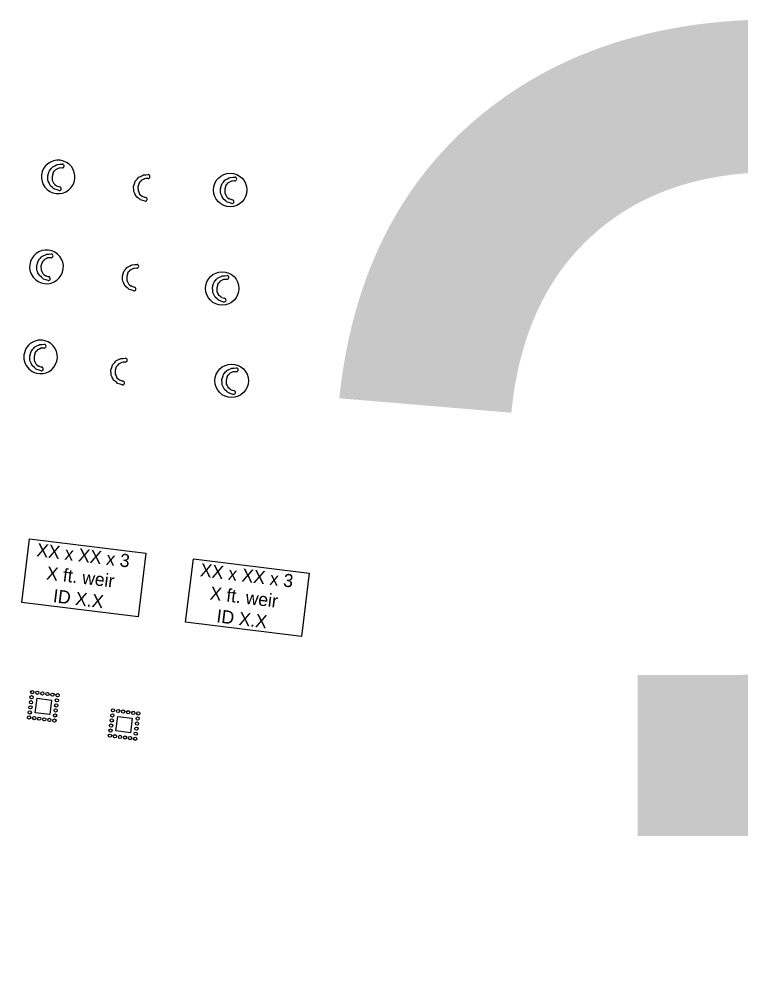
# Model space of a CAD drawing. Extents: x 2470000 to 2520000, y 340000 to 380000.
# Drawn here: x 2483280 to 2483776, y 373794 to 374460 of the extents above; entities that cross this region are included whole.
import ezdxf

# ---------------------------------------------------------------- set-up
doc = ezdxf.new("R2010")
doc.units = 0
for name, color, linetype in [('Coir Fiber Wattle Both CELL', 7, 'Continuous'), ('Coir Fiber Wattle CG CELL', 7, 'Continuous'), ('Coir Fiber Wattle Final CELL', 7, 'Continuous'), ('Coir Fiber Wattle with PAM Both CELL', 7, 'Continuous'), ('Coir Fiber Wattle with PAM CG CELL', 7, 'Continuous'), ('Coir Fiber Wattle with PAM Final CELL', 7, 'Continuous'), ('Prop Structure Anchor Unit CELL', 7, 'Continuous'), ('Scratch_Level_5', 7, 'Continuous'), ('Scratch_Level_6', 7, 'Continuous'), ('Sediment Dam B Note Both CELL', 7, 'Continuous'), ('Sediment Dam B Note Final CELL', 7, 'Continuous'), ('Wattle with PAM Both CELL', 7, 'Continuous'), ('Wattle with PAM CG CELL', 7, 'Continuous'), ('Wattle with PAM Final CELL', 7, 'Continuous')]:
    doc.layers.add(name, color=color, linetype=linetype)

msp = doc.modelspace()

# ---------------------------------------------------------------- linework, layer by layer
at = {"layer": 'Coir Fiber Wattle Both CELL'}
for p, q in [((2483354.84, 374285.25), (2483354.07, 374282.74)), ((2483354.07, 374282.73), (2483354.07, 374282.74)), ((2483354.07, 374282.73), (2483354.19, 374280.19)), ((2483354.84, 374285.25), (2483355.59, 374286.18)), ((2483356.29, 374287.05), (2483355.59, 374286.18)), ((2483356.29, 374287.05), (2483356.44, 374287.23)), ((2483357.74, 374287.88), (2483356.44, 374287.23)), ((2483358.72, 374288.37), (2483357.74, 374287.88)), ((2483359.51, 374288.41), (2483358.72, 374288.37)), ((2483361.07, 374288.5), (2483359.51, 374288.41)), ((2483354.19, 374280.19), (2483354.69, 374279.1)), ((2483354.69, 374279.1), (2483355.3, 374277.79)), ((2483355.3, 374277.79), (2483356.09, 374277.13)), ((2483356.09, 374277.13), (2483357.23, 374276.18)), ((2483357.54, 374276.08), (2483357.23, 374276.18)), ((2483357.54, 374276.08), (2483359.32, 374275.51))]:
    msp.add_line(p, q, dxfattribs=at)
msp.add_lwpolyline([(2483359, 374272.93), (2483357.51, 374273.39), (2483355.77, 374273.92), (2483355.12, 374274.45), (2483354.35, 374275.09), (2483352.96, 374276.24), (2483352.94, 374276.27), (2483352.75, 374276.67), (2483352.72, 374276.74), (2483352.29, 374277.59), (2483352, 374278.19), (2483351.36, 374279.51), (2483351.29, 374280.55), (2483351.12, 374283.09), (2483351.12, 374283.1), (2483351.93, 374285.61), (2483352.24, 374286.59), (2483352.98, 374287.45), (2483353.13, 374287.63), (2483353.76, 374288.37), (2483354.23, 374288.92), (2483354.35, 374289.05), (2483354.58, 374289.33), (2483354.59, 374289.33), (2483355.95, 374289.99), (2483357.16, 374290.57), (2483357.89, 374290.93), (2483359.64, 374291.05), (2483361.19, 374291.16)], dxfattribs=at)
for centre, radius, start in [((2483361.02, 374289.83), 1.33, 271.87949), ((2483359.16, 374274.22), 1.3, 262.99213)]:
    msp.add_arc(centre, radius, start, 82.99213, dxfattribs=at)
at = {"layer": 'Coir Fiber Wattle CG CELL'}
for p, q in [((2483363.97, 374348.72), (2483363.27, 374347.85)), ((2483363.97, 374348.72), (2483364.12, 374348.9)), ((2483365.42, 374349.55), (2483364.12, 374348.9)), ((2483366.41, 374350.04), (2483365.42, 374349.55)), ((2483367.2, 374350.08), (2483366.41, 374350.04)), ((2483368.75, 374350.17), (2483367.2, 374350.08)), ((2483362.53, 374346.92), (2483361.75, 374344.41)), ((2483361.75, 374344.4), (2483361.75, 374344.41)), ((2483361.75, 374344.4), (2483361.87, 374341.86)), ((2483362.53, 374346.92), (2483363.27, 374347.85)), ((2483361.87, 374341.86), (2483362.37, 374340.77)), ((2483362.37, 374340.77), (2483362.98, 374339.45)), ((2483362.98, 374339.45), (2483363.77, 374338.8)), ((2483363.77, 374338.8), (2483364.91, 374337.85)), ((2483365.23, 374337.75), (2483364.91, 374337.85)), ((2483365.23, 374337.75), (2483367, 374337.18))]:
    msp.add_line(p, q, dxfattribs=at)
msp.add_lwpolyline([(2483366.68, 374334.6), (2483365.19, 374335.06), (2483363.45, 374335.58), (2483362.81, 374336.12), (2483362.03, 374336.76), (2483360.64, 374337.9), (2483360.63, 374337.94), (2483360.43, 374338.34), (2483360.4, 374338.4), (2483359.98, 374339.26), (2483359.68, 374339.86), (2483359.04, 374341.18), (2483358.97, 374342.22), (2483358.8, 374344.76), (2483358.8, 374344.77), (2483359.61, 374347.28), (2483359.93, 374348.26), (2483360.66, 374349.12), (2483360.82, 374349.3), (2483361.44, 374350.03), (2483361.92, 374350.59), (2483362.03, 374350.72), (2483362.27, 374351), (2483362.27, 374351), (2483363.63, 374351.66), (2483364.84, 374352.24), (2483365.57, 374352.6), (2483367.32, 374352.72), (2483368.87, 374352.83)], dxfattribs=at)
for centre, radius, start in [((2483368.7, 374351.5), 1.33, 271.87949), ((2483366.84, 374335.89), 1.3, 262.99213)]:
    msp.add_arc(centre, radius, start, 82.99213, dxfattribs=at)
at = {"layer": 'Coir Fiber Wattle Final CELL'}
for p, q in [((2483348.35, 374222.46), (2483347.65, 374221.6)), ((2483348.35, 374222.46), (2483348.5, 374222.65)), ((2483349.8, 374223.29), (2483348.5, 374222.65)), ((2483350.79, 374223.78), (2483349.8, 374223.29)), ((2483351.58, 374223.83), (2483350.79, 374223.78)), ((2483353.13, 374223.91), (2483351.58, 374223.83)), ((2483346.91, 374220.67), (2483346.13, 374218.16)), ((2483346.13, 374218.14), (2483346.13, 374218.16)), ((2483346.13, 374218.14), (2483346.25, 374215.61)), ((2483346.25, 374215.61), (2483346.75, 374214.51)), ((2483346.91, 374220.67), (2483347.65, 374221.6)), ((2483346.75, 374214.51), (2483347.36, 374213.2)), ((2483347.36, 374213.2), (2483348.15, 374212.54)), ((2483348.15, 374212.54), (2483349.29, 374211.6)), ((2483349.6, 374211.5), (2483349.29, 374211.6)), ((2483349.6, 374211.5), (2483351.38, 374210.93))]:
    msp.add_line(p, q, dxfattribs=at)
msp.add_lwpolyline([(2483351.06, 374208.35), (2483349.57, 374208.8), (2483347.83, 374209.33), (2483347.19, 374209.86), (2483346.41, 374210.51), (2483345.02, 374211.65), (2483345.01, 374211.69), (2483344.81, 374212.08), (2483344.78, 374212.15), (2483344.36, 374213.01), (2483344.06, 374213.61), (2483343.42, 374214.92), (2483343.35, 374215.96), (2483343.18, 374218.51), (2483343.18, 374218.52), (2483343.99, 374221.03), (2483344.31, 374222.01), (2483345.04, 374222.87), (2483345.19, 374223.05), (2483345.82, 374223.78), (2483346.29, 374224.34), (2483346.41, 374224.47), (2483346.65, 374224.74), (2483346.65, 374224.75), (2483348.01, 374225.41), (2483349.22, 374225.99), (2483349.95, 374226.34), (2483351.7, 374226.46), (2483353.25, 374226.57)], dxfattribs=at)
for centre, radius, start in [((2483353.08, 374225.25), 1.33, 271.87949), ((2483351.22, 374209.64), 1.3, 262.99213)]:
    msp.add_arc(centre, radius, start, 82.99213, dxfattribs=at)
at = {"layer": 'Coir Fiber Wattle with PAM Both CELL'}
for p, q in [((2483416.69, 374277.58), (2483415.92, 374275.06)), ((2483416.69, 374277.58), (2483417.44, 374278.5)), ((2483418.14, 374279.37), (2483417.44, 374278.5)), ((2483418.14, 374279.37), (2483418.28, 374279.55)), ((2483419.58, 374280.2), (2483418.28, 374279.55)), ((2483420.57, 374280.69), (2483419.58, 374280.2)), ((2483421.36, 374280.74), (2483420.57, 374280.69)), ((2483422.91, 374280.82), (2483421.36, 374280.74)), ((2483415.92, 374275.05), (2483415.92, 374275.06)), ((2483415.92, 374275.05), (2483416.03, 374272.51)), ((2483416.03, 374272.51), (2483416.54, 374271.42)), ((2483416.54, 374271.42), (2483417.15, 374270.11)), ((2483417.15, 374270.11), (2483417.94, 374269.45)), ((2483417.94, 374269.45), (2483419.07, 374268.5)), ((2483419.39, 374268.4), (2483419.07, 374268.5)), ((2483419.39, 374268.4), (2483421.16, 374267.83))]:
    msp.add_line(p, q, dxfattribs=at)
msp.add_lwpolyline([(2483420.85, 374265.26), (2483419.35, 374265.71), (2483417.62, 374266.24), (2483416.97, 374266.77), (2483416.19, 374267.41), (2483414.81, 374268.56), (2483414.79, 374268.59), (2483414.6, 374268.99), (2483414.56, 374269.06), (2483414.14, 374269.92), (2483413.85, 374270.51), (2483413.2, 374271.83), (2483413.13, 374272.87), (2483412.97, 374275.41), (2483412.97, 374275.42), (2483413.78, 374277.94), (2483414.09, 374278.92), (2483414.83, 374279.78), (2483414.98, 374279.96), (2483415.61, 374280.69), (2483416.08, 374281.24), (2483416.19, 374281.37), (2483416.43, 374281.65), (2483416.44, 374281.66), (2483417.8, 374282.31), (2483419.01, 374282.9), (2483419.74, 374283.25), (2483421.49, 374283.37), (2483423.03, 374283.48)], dxfattribs=at)
msp.add_circle((2483419.69, 374274.57), 11.5, dxfattribs=at)
for centre, radius, start in [((2483422.87, 374282.15), 1.33, 271.87949), ((2483421, 374266.54), 1.3, 262.99213)]:
    msp.add_arc(centre, radius, start, 82.99213, dxfattribs=at)
at = {"layer": 'Coir Fiber Wattle with PAM CG CELL'}
for p, q in [((2483422.17, 374345.29), (2483421.39, 374342.78)), ((2483421.39, 374342.77), (2483421.39, 374342.78)), ((2483421.39, 374342.77), (2483421.51, 374340.23)), ((2483422.17, 374345.29), (2483422.91, 374346.22)), ((2483423.61, 374347.08), (2483422.91, 374346.22)), ((2483423.61, 374347.08), (2483423.76, 374347.27)), ((2483425.06, 374347.91), (2483423.76, 374347.27)), ((2483426.05, 374348.4), (2483425.06, 374347.91)), ((2483426.84, 374348.45), (2483426.05, 374348.4)), ((2483428.39, 374348.53), (2483426.84, 374348.45)), ((2483421.51, 374340.23), (2483422.01, 374339.13)), ((2483422.01, 374339.13), (2483422.62, 374337.82)), ((2483422.62, 374337.82), (2483423.41, 374337.16)), ((2483423.41, 374337.16), (2483424.55, 374336.22)), ((2483424.86, 374336.12), (2483424.55, 374336.22)), ((2483424.86, 374336.12), (2483426.64, 374335.55))]:
    msp.add_line(p, q, dxfattribs=at)
msp.add_lwpolyline([(2483426.32, 374332.97), (2483424.83, 374333.42), (2483423.09, 374333.95), (2483422.45, 374334.48), (2483421.67, 374335.13), (2483420.28, 374336.27), (2483420.27, 374336.31), (2483420.07, 374336.71), (2483420.04, 374336.77), (2483419.62, 374337.63), (2483419.32, 374338.23), (2483418.68, 374339.54), (2483418.61, 374340.58), (2483418.44, 374343.13), (2483418.44, 374343.14), (2483419.25, 374345.65), (2483419.57, 374346.63), (2483420.3, 374347.49), (2483420.45, 374347.67), (2483421.08, 374348.4), (2483421.55, 374348.96), (2483421.67, 374349.09), (2483421.91, 374349.37), (2483421.91, 374349.37), (2483423.27, 374350.03), (2483424.48, 374350.61), (2483425.21, 374350.96), (2483426.96, 374351.09), (2483428.51, 374351.19)], dxfattribs=at)
msp.add_circle((2483425.16, 374342.29), 11.5, dxfattribs=at)
for centre, radius, start in [((2483428.34, 374349.87), 1.33, 271.87949), ((2483426.48, 374334.26), 1.3, 262.99213)]:
    msp.add_arc(centre, radius, start, 82.99213, dxfattribs=at)
at = {"layer": 'Coir Fiber Wattle with PAM Final CELL'}
for p, q in [((2483424.58, 374215.89), (2483423.88, 374215.02)), ((2483424.58, 374215.89), (2483424.73, 374216.07)), ((2483426.03, 374216.72), (2483424.73, 374216.07)), ((2483427.02, 374217.21), (2483426.03, 374216.72)), ((2483427.81, 374217.25), (2483427.02, 374217.21)), ((2483429.36, 374217.34), (2483427.81, 374217.25)), ((2483423.14, 374214.1), (2483422.36, 374211.58)), ((2483422.36, 374211.57), (2483422.36, 374211.58)), ((2483422.36, 374211.57), (2483422.48, 374209.03)), ((2483422.48, 374209.03), (2483422.98, 374207.94)), ((2483423.14, 374214.1), (2483423.88, 374215.02)), ((2483422.98, 374207.94), (2483423.59, 374206.63)), ((2483423.59, 374206.63), (2483424.38, 374205.97)), ((2483424.38, 374205.97), (2483425.52, 374205.02)), ((2483425.83, 374204.92), (2483425.52, 374205.02)), ((2483425.83, 374204.92), (2483427.61, 374204.35))]:
    msp.add_line(p, q, dxfattribs=at)
msp.add_lwpolyline([(2483427.29, 374201.77), (2483425.8, 374202.23), (2483424.06, 374202.76), (2483423.42, 374203.29), (2483422.64, 374203.93), (2483421.25, 374205.08), (2483421.24, 374205.11), (2483421.04, 374205.51), (2483421.01, 374205.58), (2483420.59, 374206.43), (2483420.29, 374207.03), (2483419.65, 374208.35), (2483419.58, 374209.39), (2483419.41, 374211.93), (2483419.41, 374211.94), (2483420.22, 374214.45), (2483420.54, 374215.43), (2483421.27, 374216.29), (2483421.42, 374216.48), (2483422.05, 374217.21), (2483422.52, 374217.76), (2483422.64, 374217.89), (2483422.87, 374218.17), (2483422.88, 374218.17), (2483424.24, 374218.83), (2483425.45, 374219.42), (2483426.18, 374219.77), (2483427.93, 374219.89), (2483429.48, 374220)], dxfattribs=at)
msp.add_circle((2483426.13, 374211.09), 11.5, dxfattribs=at)
for centre, radius, start in [((2483429.31, 374218.67), 1.33, 271.87949), ((2483427.45, 374203.06), 1.3, 262.99213)]:
    msp.add_arc(centre, radius, start, 82.99213, dxfattribs=at)
at = {"layer": 'Prop Structure Anchor Unit CELL'}
msp.add_lwpolyline([(2483292.48, 373992.86), (2483302.4, 373991.64), (2483301.18, 373981.72), (2483291.26, 373982.95)], close=True, dxfattribs=at)
for centre in [(2483289.21, 373997.06), (2483292.68, 373996.64), (2483296.15, 373996.21), (2483299.63, 373995.78), (2483303.1, 373995.35), (2483306.57, 373994.93), (2483288.35, 373990.11), (2483288.78, 373993.59), (2483306.15, 373991.45), (2483287.5, 373983.17), (2483287.92, 373986.64), (2483305.29, 373984.5), (2483305.72, 373987.98), (2483287.07, 373979.69), (2483290.54, 373979.27), (2483294.02, 373978.84), (2483297.49, 373978.41), (2483300.96, 373977.98), (2483304.44, 373977.56), (2483304.87, 373981.03)]:
    msp.add_circle(centre, 1.12, dxfattribs=at)
at = {"layer": 'Scratch_Level_5'}
msp.add_lwpolyline([(2483347.93, 373980.35), (2483357.85, 373979.13), (2483356.63, 373969.2), (2483346.71, 373970.44)], close=True, dxfattribs=at)
for centre in [(2483344.66, 373984.55), (2483348.13, 373984.12), (2483351.61, 373983.69), (2483355.08, 373983.27), (2483358.55, 373982.84), (2483362.03, 373982.41), (2483343.8, 373977.6), (2483344.23, 373981.07), (2483361.17, 373975.46), (2483361.6, 373978.94), (2483342.95, 373970.65), (2483343.38, 373974.13), (2483360.32, 373968.52), (2483360.74, 373971.99), (2483342.52, 373967.18), (2483345.99, 373966.75), (2483349.47, 373966.32), (2483352.94, 373965.9), (2483356.42, 373965.47), (2483359.89, 373965.04)]:
    msp.add_circle(centre, 1.12, dxfattribs=at)
at = {"layer": 'Sediment Dam B Note Both CELL'}
msp.add_lwpolyline([(2483287.36, 374102.39), (2483367.29, 374092.57), (2483361.92, 374048.92), (2483281.99, 374058.75)], close=True, dxfattribs=at)
at = {"layer": 'Sediment Dam B Note Final CELL'}
msp.add_lwpolyline([(2483399.86, 374088.73), (2483479.46, 374078.95), (2483474.09, 374035.3), (2483394.49, 374045.09)], close=True, dxfattribs=at)
at = {"layer": 'Wattle with PAM Both CELL'}
for p, q in [((2483299.87, 374295.53), (2483298.88, 374295.04)), ((2483300.66, 374295.57), (2483299.87, 374295.53)), ((2483302.21, 374295.66), (2483300.66, 374295.57)), ((2483295.99, 374292.41), (2483295.21, 374289.9)), ((2483295.21, 374289.89), (2483295.21, 374289.9)), ((2483295.21, 374289.89), (2483295.33, 374287.35)), ((2483295.99, 374292.41), (2483296.73, 374293.34)), ((2483297.43, 374294.21), (2483296.73, 374293.34)), ((2483297.43, 374294.21), (2483297.58, 374294.39)), ((2483298.88, 374295.04), (2483297.58, 374294.39)), ((2483295.33, 374287.35), (2483295.83, 374286.26)), ((2483295.83, 374286.26), (2483296.44, 374284.95)), ((2483296.44, 374284.95), (2483297.23, 374284.29)), ((2483297.23, 374284.29), (2483298.37, 374283.34)), ((2483298.69, 374283.24), (2483298.37, 374283.34)), ((2483298.69, 374283.24), (2483300.46, 374282.67))]:
    msp.add_line(p, q, dxfattribs=at)
msp.add_lwpolyline([(2483300.14, 374280.09), (2483298.65, 374280.55), (2483296.91, 374281.07), (2483296.27, 374281.61), (2483295.49, 374282.25), (2483294.1, 374283.39), (2483294.09, 374283.43), (2483293.89, 374283.83), (2483293.86, 374283.89), (2483293.44, 374284.75), (2483293.14, 374285.35), (2483292.5, 374286.67), (2483292.43, 374287.71), (2483292.26, 374290.25), (2483292.26, 374290.26), (2483293.07, 374292.77), (2483293.39, 374293.75), (2483294.12, 374294.61), (2483294.28, 374294.79), (2483294.9, 374295.52), (2483295.37, 374296.08), (2483295.49, 374296.21), (2483295.73, 374296.49), (2483295.73, 374296.49), (2483297.09, 374297.15), (2483298.3, 374297.73), (2483299.03, 374298.09), (2483300.78, 374298.21), (2483302.33, 374298.32)], dxfattribs=at)
for centre, radius, start, end in [((2483298.98, 374289.41), 11.62, 82.99213, 262.99213), ((2483298.98, 374289.41), 11.62, 262.99213, 82.99213), ((2483302.16, 374296.99), 1.33, 271.87949, 82.99213), ((2483300.3, 374281.38), 1.3, 262.99213, 82.99213)]:
    msp.add_arc(centre, radius, start, end, dxfattribs=at)
at = {"layer": 'Wattle with PAM CG CELL'}
for p, q in [((2483305.02, 374355.96), (2483304.32, 374355.1)), ((2483305.02, 374355.96), (2483304.32, 374355.1)), ((2483305.02, 374355.96), (2483305.17, 374356.14)), ((2483305.02, 374355.96), (2483305.17, 374356.14)), ((2483306.47, 374356.79), (2483305.17, 374356.14)), ((2483306.47, 374356.79), (2483305.17, 374356.14)), ((2483307.46, 374357.28), (2483306.47, 374356.79)), ((2483307.46, 374357.28), (2483306.47, 374356.79)), ((2483308.25, 374357.33), (2483307.46, 374357.28)), ((2483308.25, 374357.33), (2483307.46, 374357.28)), ((2483309.8, 374357.41), (2483308.25, 374357.33)), ((2483309.8, 374357.41), (2483308.25, 374357.33)), ((2483303.58, 374354.17), (2483302.8, 374351.66)), ((2483303.58, 374354.17), (2483302.8, 374351.66)), ((2483302.8, 374351.64), (2483302.8, 374351.66)), ((2483302.8, 374351.64), (2483302.8, 374351.66)), ((2483302.8, 374351.64), (2483302.92, 374349.1)), ((2483302.8, 374351.64), (2483302.92, 374349.1)), ((2483302.92, 374349.1), (2483303.42, 374348.01)), ((2483302.92, 374349.1), (2483303.42, 374348.01)), ((2483303.58, 374354.17), (2483304.32, 374355.1)), ((2483303.58, 374354.17), (2483304.32, 374355.1)), ((2483303.42, 374348.01), (2483304.03, 374346.7)), ((2483303.42, 374348.01), (2483304.03, 374346.7)), ((2483304.03, 374346.7), (2483304.82, 374346.04)), ((2483304.03, 374346.7), (2483304.82, 374346.04)), ((2483304.82, 374346.04), (2483305.96, 374345.1)), ((2483304.82, 374346.04), (2483305.96, 374345.1)), ((2483306.28, 374344.99), (2483305.96, 374345.1)), ((2483306.28, 374344.99), (2483305.96, 374345.1)), ((2483306.28, 374344.99), (2483308.05, 374344.43)), ((2483306.28, 374344.99), (2483308.05, 374344.43))]:
    msp.add_line(p, q, dxfattribs=at)
msp.add_lwpolyline([(2483307.73, 374341.85), (2483306.24, 374342.3), (2483304.5, 374342.83), (2483303.86, 374343.36), (2483303.08, 374344.01), (2483301.7, 374345.15), (2483301.68, 374345.19), (2483301.48, 374345.58), (2483301.45, 374345.65), (2483301.03, 374346.51), (2483300.73, 374347.11), (2483300.09, 374348.42), (2483300.02, 374349.46), (2483299.85, 374352.01), (2483299.86, 374352.02), (2483300.66, 374354.53), (2483300.98, 374355.51), (2483301.71, 374356.37), (2483301.87, 374356.55), (2483302.49, 374357.28), (2483302.97, 374357.84), (2483303.08, 374357.96), (2483303.32, 374358.24), (2483303.32, 374358.25), (2483304.68, 374358.91), (2483305.89, 374359.49), (2483306.62, 374359.84), (2483308.37, 374359.96), (2483309.92, 374360.07)], dxfattribs=at)
msp.add_lwpolyline([(2483307.73, 374341.85), (2483306.24, 374342.3), (2483304.5, 374342.83), (2483303.86, 374343.36), (2483303.08, 374344.01), (2483301.7, 374345.15), (2483301.68, 374345.19), (2483301.48, 374345.58), (2483301.45, 374345.65), (2483301.03, 374346.51), (2483300.73, 374347.11), (2483300.09, 374348.42), (2483300.02, 374349.46), (2483299.85, 374352.01), (2483299.86, 374352.02), (2483300.66, 374354.53), (2483300.98, 374355.51), (2483301.71, 374356.37), (2483301.87, 374356.55), (2483302.49, 374357.28), (2483302.97, 374357.84), (2483303.08, 374357.96), (2483303.32, 374358.24), (2483303.32, 374358.25), (2483304.68, 374358.91), (2483305.89, 374359.49), (2483306.62, 374359.84), (2483308.37, 374359.96), (2483309.92, 374360.07)], dxfattribs=at)
for centre, radius, start, end in [((2483307.01, 374351.25), 11.5, 82.99213, 262.99213), ((2483307.01, 374351.25), 11.5, 262.99213, 82.99213), ((2483309.76, 374358.75), 1.33, 271.87949, 82.99213), ((2483309.76, 374358.75), 1.33, 271.87949, 82.99213), ((2483307.89, 374343.14), 1.3, 262.99213, 82.99213), ((2483307.89, 374343.14), 1.3, 262.99213, 82.99213)]:
    msp.add_arc(centre, radius, start, end, dxfattribs=at)
at = {"layer": 'Wattle with PAM Final CELL'}
for p, q in [((2483291.2, 374230.31), (2483290.43, 374227.8)), ((2483291.2, 374230.3), (2483290.43, 374227.79)), ((2483291.2, 374230.31), (2483291.95, 374231.24)), ((2483291.2, 374230.3), (2483291.95, 374231.23)), ((2483292.65, 374232.1), (2483291.95, 374231.24)), ((2483292.65, 374232.09), (2483291.95, 374231.23)), ((2483292.65, 374232.1), (2483292.8, 374232.29)), ((2483292.65, 374232.09), (2483292.79, 374232.28)), ((2483294.09, 374232.92), (2483292.79, 374232.28)), ((2483294.09, 374232.93), (2483292.8, 374232.29)), ((2483295.08, 374233.43), (2483294.09, 374232.93)), ((2483295.08, 374233.41), (2483294.09, 374232.92)), ((2483295.87, 374233.47), (2483295.08, 374233.43)), ((2483295.87, 374233.46), (2483295.08, 374233.41)), ((2483297.42, 374233.56), (2483295.87, 374233.47)), ((2483297.42, 374233.54), (2483295.87, 374233.46)), ((2483290.43, 374227.79), (2483290.43, 374227.8)), ((2483290.43, 374227.79), (2483290.54, 374225.25)), ((2483290.43, 374227.78), (2483290.43, 374227.79)), ((2483290.43, 374227.78), (2483290.54, 374225.24)), ((2483290.54, 374225.25), (2483291.05, 374224.16)), ((2483290.54, 374225.24), (2483291.05, 374224.14)), ((2483291.05, 374224.16), (2483291.66, 374222.84)), ((2483291.05, 374224.14), (2483291.66, 374222.83)), ((2483291.66, 374222.84), (2483292.45, 374222.19)), ((2483291.66, 374222.83), (2483292.45, 374222.17)), ((2483292.45, 374222.19), (2483293.58, 374221.24)), ((2483292.45, 374222.17), (2483293.58, 374221.23)), ((2483293.9, 374221.14), (2483293.58, 374221.24)), ((2483293.9, 374221.13), (2483293.58, 374221.23)), ((2483293.9, 374221.14), (2483295.67, 374220.57)), ((2483293.9, 374221.13), (2483295.67, 374220.56))]:
    msp.add_line(p, q, dxfattribs=at)
for points in [[(2483295.36, 374217.99), (2483293.86, 374218.45), (2483292.13, 374218.97), (2483291.48, 374219.51), (2483290.7, 374220.15), (2483289.32, 374221.29), (2483289.3, 374221.33), (2483289.11, 374221.73), (2483289.07, 374221.79), (2483288.65, 374222.65), (2483288.36, 374223.25), (2483287.71, 374224.57), (2483287.64, 374225.6), (2483287.48, 374228.15), (2483287.48, 374228.16), (2483288.29, 374230.67), (2483288.6, 374231.65), (2483289.34, 374232.51), (2483289.49, 374232.69), (2483290.12, 374233.42), (2483290.59, 374233.98), (2483290.7, 374234.11), (2483290.94, 374234.39), (2483290.95, 374234.39), (2483292.31, 374235.05), (2483293.52, 374235.63), (2483294.25, 374235.98), (2483296, 374236.11), (2483297.54, 374236.21)], [(2483295.35, 374217.98), (2483293.86, 374218.43), (2483292.13, 374218.96), (2483291.48, 374219.49), (2483290.7, 374220.14), (2483289.32, 374221.28), (2483289.3, 374221.32), (2483289.11, 374221.72), (2483289.07, 374221.78), (2483288.65, 374222.64), (2483288.36, 374223.24), (2483287.71, 374224.55), (2483287.64, 374225.59), (2483287.48, 374228.14), (2483287.48, 374228.15), (2483288.29, 374230.66), (2483288.6, 374231.64), (2483289.34, 374232.5), (2483289.49, 374232.68), (2483290.11, 374233.41), (2483290.59, 374233.97), (2483290.7, 374234.1), (2483290.94, 374234.38), (2483290.95, 374234.38), (2483292.31, 374235.04), (2483293.51, 374235.62), (2483294.24, 374235.97), (2483296, 374236.1), (2483297.54, 374236.2)]]:
    msp.add_lwpolyline(points, dxfattribs=at)
for centre, radius, start, end in [((2483294.91, 374227.53), 11.5, 75.15633, 255.63864), ((2483294.95, 374227.52), 11.5, 255.39749, 75.39749), ((2483297.38, 374234.89), 1.33, 271.87949, 82.99213), ((2483297.38, 374234.88), 1.33, 271.87949, 82.99213), ((2483295.51, 374219.27), 1.3, 262.99213, 82.99213), ((2483295.51, 374219.28), 1.3, 262.99213, 82.99213)]:
    msp.add_arc(centre, radius, start, end, dxfattribs=at)

# ---------------------------------------------------------------- texts
at = {"layer": 'Scratch_Level_6'}
msp.add_text('4387', height=1000, dxfattribs=at).set_placement((2482689.75, 373444.66))
at = {"layer": 'Sediment Dam B Note Both CELL'}
for s, p in [('XX x XX x 3', (2483291.86, 374090.56)), ('X ft. weir', (2483298.57, 374074.62)), ('ID X.X', (2483303.13, 374058.95))]:
    msp.add_text(s, height=9, rotation=352.99213, dxfattribs=at).set_placement(p)
at = {"layer": 'Sediment Dam B Note Final CELL'}
for s, p in [('XX x XX x 3', (2483404.14, 374076.76)), ('X ft. weir', (2483410.85, 374060.82)), ('ID X.X', (2483415.42, 374045.15))]:
    msp.add_text(s, height=9, rotation=352.99213, dxfattribs=at).set_placement(p)

doc.saveas('drawing.dxf')
